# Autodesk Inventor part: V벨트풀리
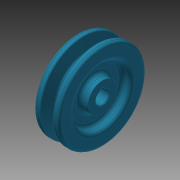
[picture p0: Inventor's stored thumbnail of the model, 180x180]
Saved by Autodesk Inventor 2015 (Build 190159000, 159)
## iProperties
Created: 2015-11
Part Number: V벨트풀리
Material: 강철, 탄소
Document SubType Name: Modeling
Designer: mduedu
Density: 1 g/cm^3
Appearance: 터키옥색
Author: mduedu
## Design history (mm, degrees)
sketch "스케치1"
  geometry: L1 (-9.5, 0)-(9.5, 0); L2 (0, 0)-(0, 32.7); L3 (-4.825, 32.7)-(-9.5, 32.7); L4 (-9.5, 32.7)-(-9.5, 0); L5 (0, 23.7)-(-2.074, 23.7); L6 (-2.074, 23.7)-(-4.825, 32.7); L7 (4.825, 32.7)-(9.5, 32.7); L8 (9.5, 32.7)-(9.5, 0); L9 (0, 23.7)-(2.074, 23.7); L10 (2.074, 23.7)-(4.825, 32.7); L11 (-9.5, 30)-(9.5, 30); 3 further points
  constraints: 22 end point, 7 point on line, 4 perpendicular, 3 symmetric about line, 1 coincident, 1 horizontal, 1 horizontal alignment, 1 midpoint, 1 vertical
  dimensions: "d0" = 19 distance of L1.start L1.end; "d2" = 65.4 diameter of L2.end L1 (derived); "d3" = 34 deg angle of L10 L6; "d4" = 6.3 distance between parallel lines of L11 L9; "d5" = 2.7 distance between parallel lines of L7 L11; "d6" = 8 distance of point (4, 30) point (-4, 30); "d7" = 60 diameter of L11 L1
revolve "회전1" sketch "스케치1" stored, may be unused: angle "d8" = 90 deg
sketch "스케치2"
  geometry: C1 r 21 at (0, 0); C2 r 11 at (0, 0); 1 further point
  constraints: 2 centre point, 2 coincident
  dimensions: "d9" = 42 diameter of C1; "d10" = 22 diameter of C2
extrude "돌출1" cut sketch "스케치2" distance "d11" = 6; taper "d12" = 0 deg
fillet "모깎기1" dims "d13" = 3
fillet "모깎기2" dims "d14" = 3
fillet "모깎기3" dims "d15" = 1, "d16" = 0.5, "d17" = 2
hole "구멍1" diameter "d20" = 10; stored, may be unused: countersink angle "d24" = 90 deg, drill point angle "d26" = 118 deg; dims "d18" = 10, "d19" = 10, "d21" = 6, "d22" = 4, "d23" = 2, "d25" = 8
sketch "스케치3"
  geometry: L1 (-1.5, 0)-(1.5, 0); L2 (1.5, 0)-(1.5, 6.4); L3 (1.5, 6.4)-(-1.5, 6.4); L4 (-1.5, 6.4)-(-1.5, 0); 2 further points
  constraints: 8 end point, 2 parallel, 1 coincident, 1 horizontal, 1 midpoint, 1 perpendicular
  dimensions: "d27" = 3 distance of L2.end L3.end; "d29" = 6.4 distance of L3.end L1.start
extrude "돌출2" cut sketch "스케치3" stored distance "d30" = 6; taper "d31" = 0 deg
chamfer "모따기1" distance "d32" = 0.5; stored, may be unused: second distance "d33" = 2, angle "d34" = 45 deg
node "솔리드1"
mirror "대칭1"
